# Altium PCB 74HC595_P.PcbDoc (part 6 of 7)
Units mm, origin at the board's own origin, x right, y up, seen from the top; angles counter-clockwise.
Board outline 89.11 x 89.03 mm, 2 copper layers (Top Layer, Bottom Layer); 552 components, 23 nets, 1488 pads, 408 vias.
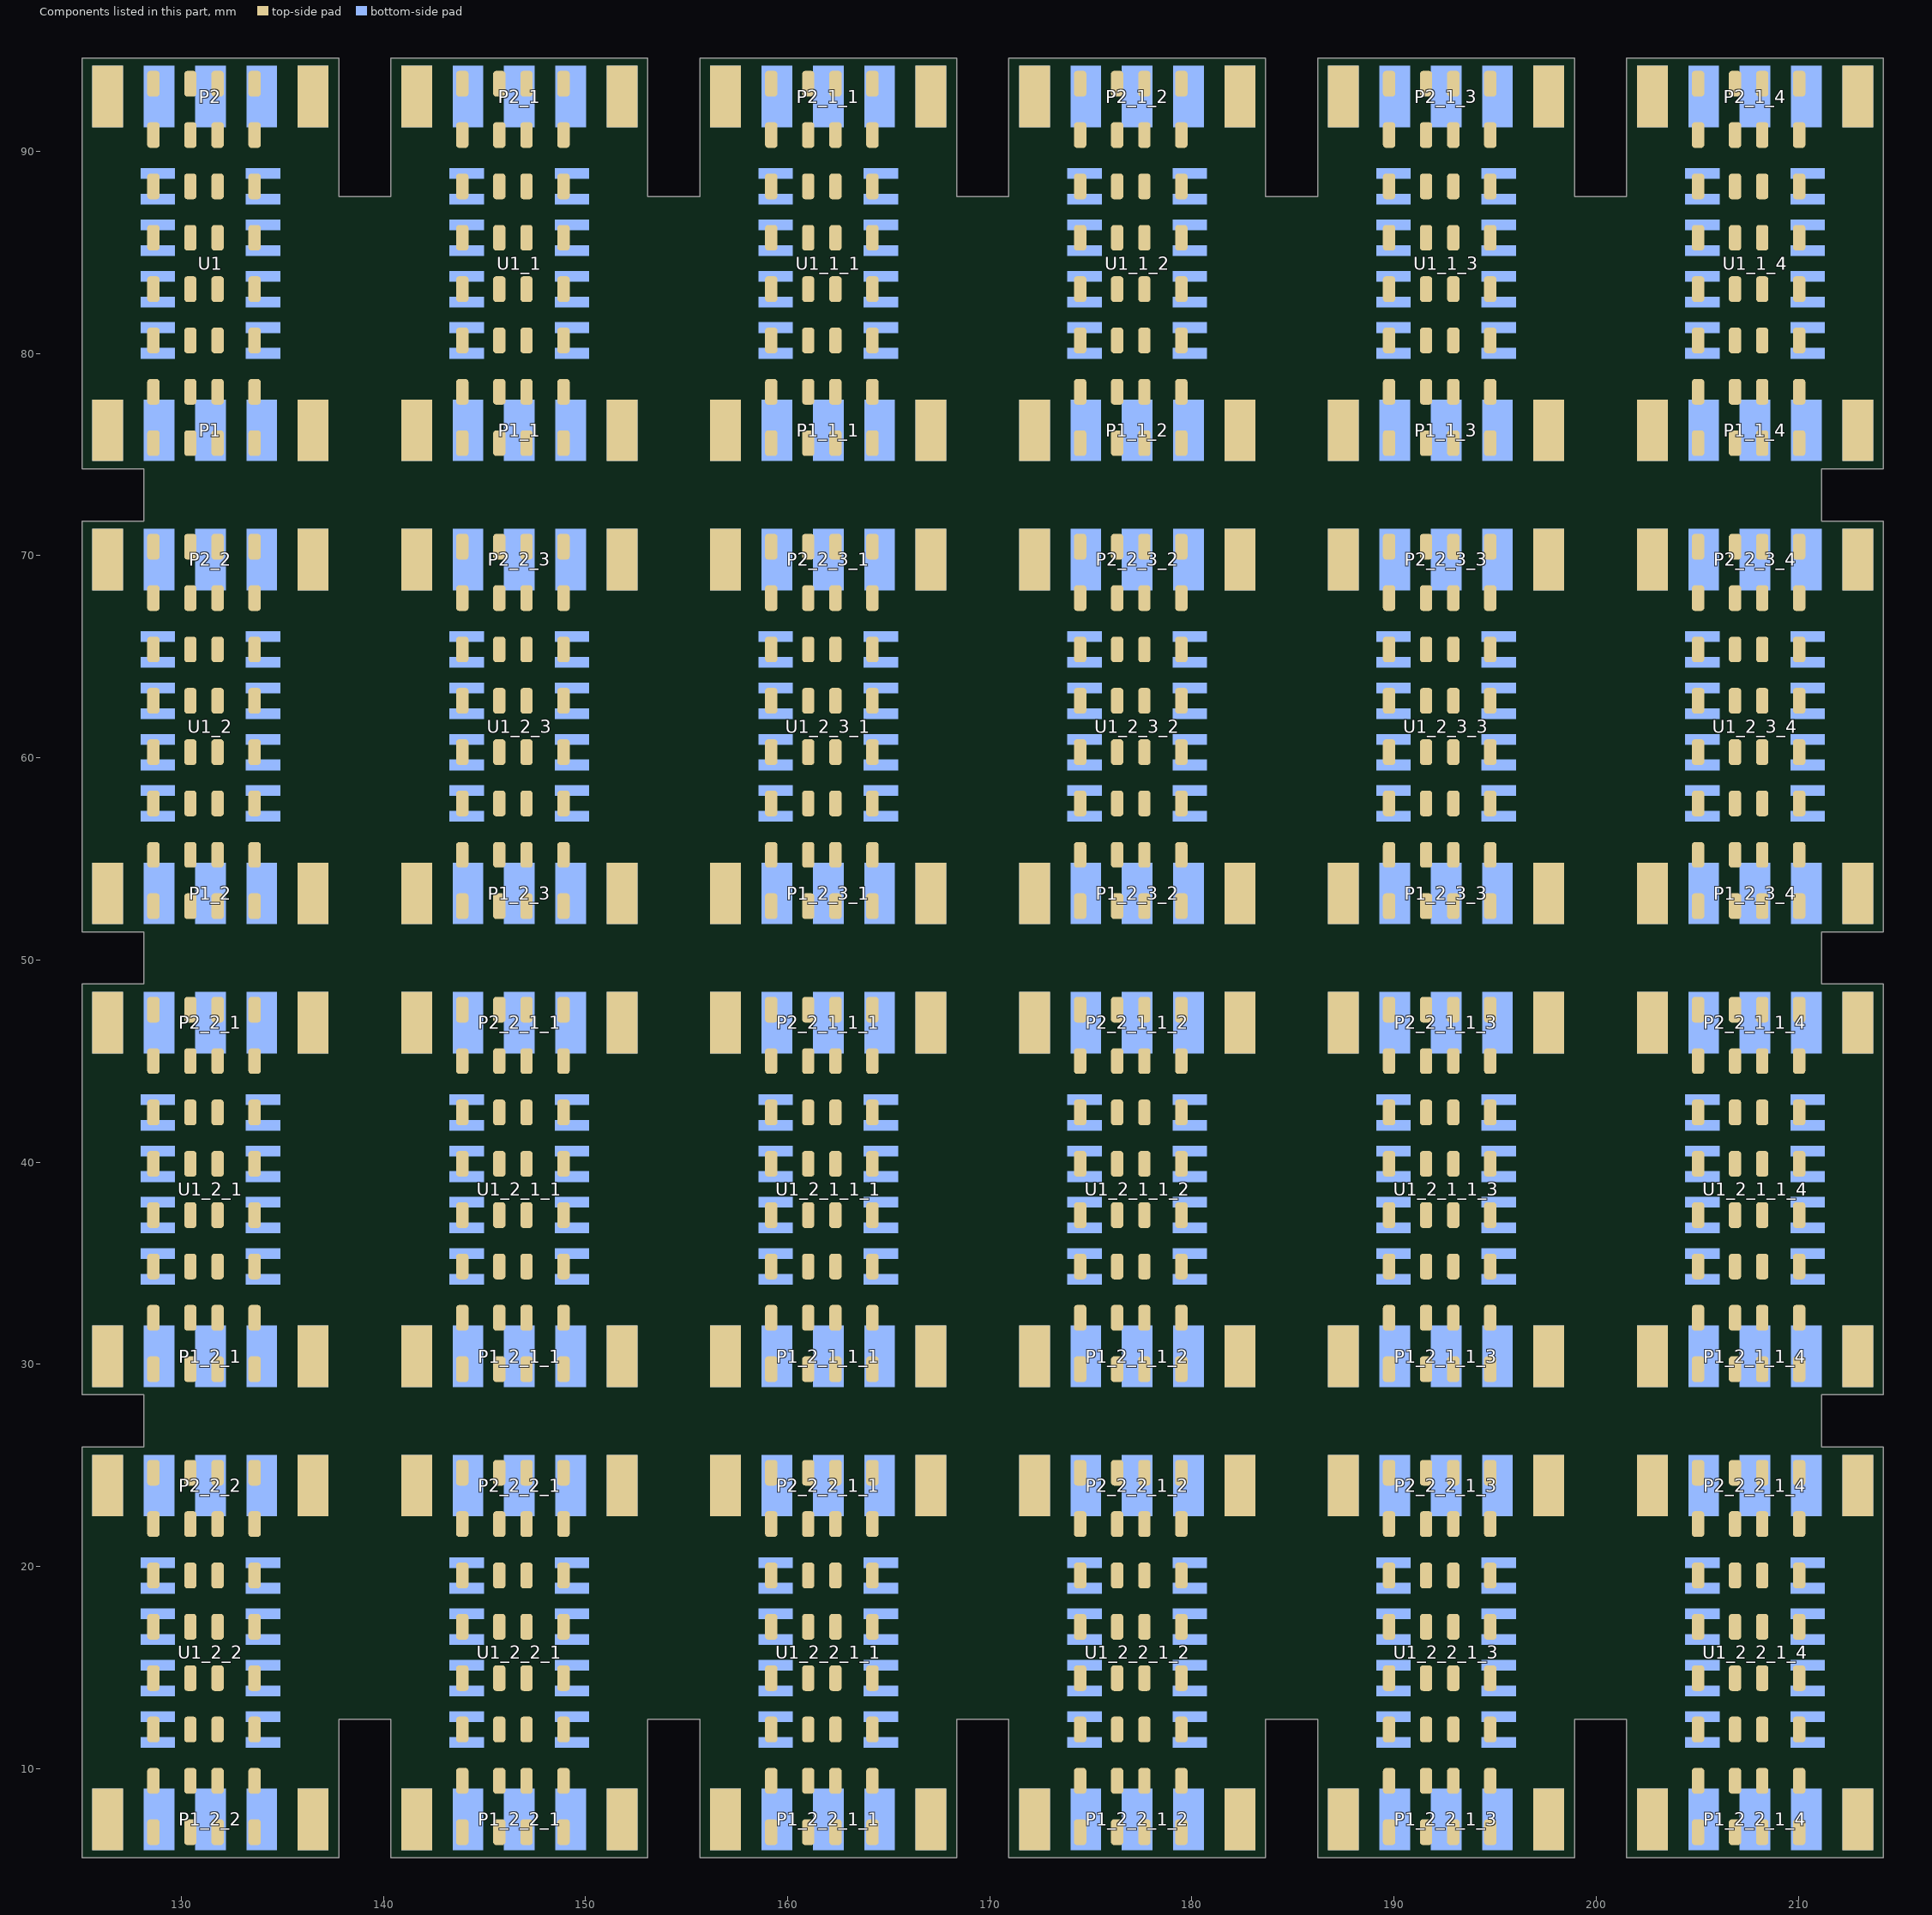
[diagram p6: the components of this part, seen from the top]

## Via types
v1: diameter 0.635, hole 0.381, Top Layer to Bottom Layer, 408 vias

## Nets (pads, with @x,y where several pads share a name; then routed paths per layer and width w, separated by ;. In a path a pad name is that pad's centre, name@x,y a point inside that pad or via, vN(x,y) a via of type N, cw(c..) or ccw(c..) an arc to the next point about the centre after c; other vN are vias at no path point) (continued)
copper on no net: (continued)
  Bottom Layer w0.381: 125.857,8.129 125.857,23.369 ; 125.857,31.031 125.857,46.271 ; 125.857,53.933 125.857,69.173 ; 125.984,17.654 128.841,17.654 ; 125.984,40.556 128.841,40.556 ; 125.984,63.458 128.841,63.458 ; v1(126.746,16.765) 126.746,11.685 127.127,11.304 128.841,11.304 128.841,7.558 ; v1(126.746,18.67) 126.746,21.21 128.905,23.369 128.905,24.004 ; v1(126.746,39.667) 126.746,34.587 127.127,34.206 128.841,34.206 128.841,30.46 ; v1(126.746,41.572) 126.746,44.112 128.905,46.271 128.905,46.906 ; v1(126.746,62.569) 126.746,57.489 127.127,57.108 128.841,57.108 128.841,53.362 ; v1(126.746,64.474) 126.746,67.014 128.905,69.173 128.905,69.808 ; v1(127.508,15.749) 127.508,13.971 127.635,13.844 128.841,13.844 130.048,13.844 131.064,12.828 131.064,7.875 131.445,7.494 ; v1(127.508,19.559) 127.508,21.074 128.152,21.718 129.921,21.718 131.445,23.242 131.445,24.004 ; v1(127.508,38.651) 127.508,36.873 127.635,36.746 128.841,36.746 130.048,36.746 131.064,35.73 131.064,30.777 131.445,30.396 ; v1(127.508,42.461) 127.508,43.976 128.152,44.62 129.921,44.62 131.445,46.144 131.445,46.906 ; v1(127.508,61.553) 127.508,59.775 127.635,59.648 128.841,59.648 130.048,59.648 131.064,58.632 131.064,53.679 131.445,53.298 ; v1(127.508,65.363) 127.508,66.878 128.152,67.522 129.921,67.522 131.445,69.046 131.445,69.808 ; 128.841,15.114 130.556,15.114 v1(131.191,15.749) 131.826,15.114 131.826,10.161 133.985,8.002 ; 128.841,16.384 130.048,16.384 130.683,17.019 131.953,17.019 132.461,16.511 132.461,10.669 133.35,9.78 137.033,9.78 ; 128.841,18.924 130.937,18.924 133.477,21.464 v1(135.89,21.464) ; 128.841,38.016 130.556,38.016 v1(131.191,38.651) 131.826,38.016 131.826,33.063 133.985,30.904 ; 128.841,39.286 130.048,39.286 130.683,39.921 131.953,39.921 132.461,39.413 132.461,33.571 133.35,32.682 137.033,32.682 ; 128.841,41.826 130.937,41.826 133.477,44.366 v1(135.89,44.366) ; 128.841,60.918 130.556,60.918 v1(131.191,61.553) 131.826,60.918 131.826,55.965 133.985,53.806 ; 128.841,62.188 130.048,62.188 130.683,62.823 131.953,62.823 132.461,62.315 132.461,56.473 133.35,55.584 137.033,55.584 ; 128.841,64.728 130.937,64.728 133.477,67.268 v1(135.89,67.268) ; 128.905,7.494 128.905,8.383 ; 128.905,30.396 128.905,31.285 ; 128.905,53.298 128.905,54.187 ; v1(131.191,20.829) 131.572,20.829 133.985,23.242 133.985,24.004 ; v1(131.191,43.731) 131.572,43.731 133.985,46.144 133.985,46.906 ; v1(131.191,66.633) 131.572,66.633 133.985,69.046 133.985,69.808 ; 134.048,11.304 v1(135.89,11.304) ; 134.048,12.574 v1(135.89,12.574) ; 134.048,13.844 v1(136.017,13.844) ; 134.048,15.114 v1(135.89,15.114) ; 134.048,16.384 v1(135.89,16.384) ; 134.048,17.654 v1(135.89,17.654) ; 134.048,18.924 v1(135.89,18.924) ; 134.048,20.194 v1(135.89,20.194) ; 134.048,34.206 v1(135.89,34.206) ; 134.048,35.476 v1(135.89,35.476) ; 134.048,36.746 v1(136.017,36.746) ; 134.048,38.016 v1(135.89,38.016) ; 134.048,39.286 v1(135.89,39.286) ; 134.048,40.556 v1(135.89,40.556) ; 134.048,41.826 v1(135.89,41.826) ; 134.048,43.096 v1(135.89,43.096) ; 134.048,57.108 v1(135.89,57.108) ; 134.048,58.378 v1(135.89,58.378) ; 134.048,59.648 v1(136.017,59.648) ; 134.048,60.918 v1(135.89,60.918) ; 134.048,62.188 v1(135.89,62.188) ; 134.048,63.458 v1(135.89,63.458) ; 134.048,64.728 v1(135.89,64.728) ; 134.048,65.998 v1(135.89,65.998) ; 137.033,8.129 137.033,9.78 ; 137.033,23.369 137.033,9.78 ; 137.033,31.031 137.033,32.682 ; 137.033,46.271 137.033,32.682 ; 137.033,53.933 137.033,55.584 ; 137.033,69.173 137.033,55.584 ; 141.139,8.129 141.139,23.369 ; 141.139,31.031 141.139,46.271 ; 141.139,53.933 141.139,69.173 ; 141.139,76.835 141.139,92.075 ; 141.266,17.654 144.123,17.654 ; 141.266,40.556 144.123,40.556 ; 141.266,63.458 144.123,63.458 ; 141.266,86.36 144.123,86.36 ; v1(142.028,16.765) 142.028,11.685 142.409,11.304 144.123,11.304 144.123,7.558 ; v1(142.028,18.67) 142.028,21.21 144.187,23.369 144.187,24.004 ; v1(142.028,39.667) 142.028,34.587 142.409,34.206 144.123,34.206 144.123,30.46 ; v1(142.028,41.572) 142.028,44.112 144.187,46.271 144.187,46.906 ; v1(142.028,62.569) 142.028,57.489 142.409,57.108 144.123,57.108 144.123,53.362 ; v1(142.028,64.474) 142.028,67.014 144.187,69.173 144.187,69.808 ; v1(142.028,85.471) 142.028,80.391 142.409,80.01 144.123,80.01 144.123,76.263 ; v1(142.028,87.376) 142.028,89.916 144.187,92.075 144.187,92.71 ; v1(142.79,15.749) 142.79,13.971 142.917,13.844 144.123,13.844 145.33,13.844 146.346,12.828 146.346,7.875 146.727,7.494 ; v1(142.79,19.559) 142.79,21.074 143.434,21.718 145.203,21.718 146.727,23.242 146.727,24.004 ; v1(142.79,38.651) 142.79,36.873 142.917,36.746 144.123,36.746 145.33,36.746 146.346,35.73 146.346,30.777 146.727,30.396 ; v1(142.79,42.461) 142.79,43.976 143.434,44.62 145.203,44.62 146.727,46.144 146.727,46.906 ; v1(142.79,61.553) 142.79,59.775 142.917,59.648 144.123,59.648 145.33,59.648 146.346,58.632 146.346,53.679 146.727,53.298 ; v1(142.79,65.363) 142.79,66.878 143.434,67.522 145.203,67.522 146.727,69.046 146.727,69.808 ; v1(142.79,84.455) 142.79,82.677 142.917,82.55 144.123,82.55 145.33,82.55 146.346,81.534 146.346,76.581 146.727,76.2 ; v1(142.79,88.265) 142.79,89.78 143.434,90.424 145.203,90.424 146.727,91.948 146.727,92.71 ; 144.123,15.114 145.838,15.114 v1(146.473,15.749) 147.108,15.114 147.108,10.161 149.267,8.002 ; 144.123,16.384 145.33,16.384 145.965,17.019 147.235,17.019 147.743,16.511 147.743,10.669 148.632,9.78 152.315,9.78 ; 144.123,18.924 146.219,18.924 148.759,21.464 v1(151.172,21.464) ; 144.123,38.016 145.838,38.016 v1(146.473,38.651) 147.108,38.016 147.108,33.063 149.267,30.904 ; 144.123,39.286 145.33,39.286 145.965,39.921 147.235,39.921 147.743,39.413 147.743,33.571 148.632,32.682 152.315,32.682 ; 144.123,41.826 146.219,41.826 148.759,44.366 v1(151.172,44.366) ; 144.123,60.918 145.838,60.918 v1(146.473,61.553) 147.108,60.918 147.108,55.965 149.267,53.806 ; 144.123,62.188 145.33,62.188 145.965,62.823 147.235,62.823 147.743,62.315 147.743,56.473 148.632,55.584 152.315,55.584 ; 144.123,64.728 146.219,64.728 148.759,67.268 v1(151.172,67.268) ; 144.123,83.82 145.838,83.82 v1(146.473,84.455) 147.108,83.82 147.108,78.867 149.267,76.708 ; 144.123,85.09 145.33,85.09 145.965,85.725 147.235,85.725 147.743,85.217 147.743,79.375 148.632,78.486 152.315,78.486 ; 144.123,87.63 146.219,87.63 148.759,90.17 v1(151.172,90.17) ; 144.187,7.494 144.187,8.383 ; 144.187,30.396 144.187,31.285 ; 144.187,53.298 144.187,54.187 ; 144.187,76.2 144.187,77.089 ; v1(146.473,20.829) 146.854,20.829 149.267,23.242 149.267,24.004 ; v1(146.473,43.731) 146.854,43.731 149.267,46.144 149.267,46.906 ; v1(146.473,66.633) 146.854,66.633 149.267,69.046 149.267,69.808 ; v1(146.473,89.535) 146.854,89.535 149.267,91.948 149.267,92.71 ; 149.33,11.304 v1(151.172,11.304) ; 149.33,12.574 v1(151.172,12.574) ; 149.33,13.844 v1(151.299,13.844) ; 149.33,15.114 v1(151.172,15.114) ; 149.33,16.384 v1(151.172,16.384) ; 149.33,17.654 v1(151.172,17.654) ; 149.33,18.924 v1(151.172,18.924) ; 149.33,20.194 v1(151.172,20.194) ; 149.33,34.206 v1(151.172,34.206) ; 149.33,35.476 v1(151.172,35.476) ; 149.33,36.746 v1(151.299,36.746) ; 149.33,38.016 v1(151.172,38.016) ; 149.33,39.286 v1(151.172,39.286) ; 149.33,40.556 v1(151.172,40.556) ; 149.33,41.826 v1(151.172,41.826) ; 149.33,43.096 v1(151.172,43.096) ; 149.33,57.108 v1(151.172,57.108) ; 149.33,58.378 v1(151.172,58.378) ; 149.33,59.648 v1(151.299,59.648) ; 149.33,60.918 v1(151.172,60.918) ; 149.33,62.188 v1(151.172,62.188) ; 149.33,63.458 v1(151.172,63.458) ; 149.33,64.728 v1(151.172,64.728) ; 149.33,65.998 v1(151.172,65.998) ; 149.33,80.01 v1(151.172,80.01) ; 149.33,81.28 v1(151.172,81.28) ; 149.33,82.55 v1(151.299,82.55) ; 149.33,83.82 v1(151.172,83.82) ; 149.33,85.09 v1(151.172,85.09) ; 149.33,86.36 v1(151.172,86.36) ; 149.33,87.63 v1(151.172,87.63) ; 149.33,88.9 v1(151.172,88.9) ; 152.315,8.129 152.315,9.78 ; 152.315,23.369 152.315,9.78 ; 152.315,31.031 152.315,32.682 ; 152.315,46.271 152.315,32.682 ; 152.315,53.933 152.315,55.584 ; 152.315,69.173 152.315,55.584 ; 152.315,76.835 152.315,78.486 ; 152.315,92.075 152.315,78.486 ; 156.421,8.129 156.421,23.369 ; 156.421,31.031 156.421,46.271 ; 156.421,53.933 156.421,69.173 ; 156.421,76.835 156.421,92.075 ; 156.548,17.654 159.405,17.654 ; 156.548,40.556 159.405,40.556 ; 156.548,63.458 159.405,63.458 ; 156.548,86.36 159.405,86.36 ; v1(157.31,16.765) 157.31,11.685 157.691,11.304 159.405,11.304 159.405,7.558 ; v1(157.31,18.67) 157.31,21.21 159.469,23.369 159.469,24.004 ; v1(157.31,39.667) 157.31,34.587 157.691,34.206 159.405,34.206 159.405,30.46 ; v1(157.31,41.572) 157.31,44.112 159.469,46.271 159.469,46.906 ; v1(157.31,62.569) 157.31,57.489 157.691,57.108 159.405,57.108 159.405,53.362 ; v1(157.31,64.474) 157.31,67.014 159.469,69.173 159.469,69.808 ; v1(157.31,85.471) 157.31,80.391 157.691,80.01 159.405,80.01 159.405,76.263 ; v1(157.31,87.376) 157.31,89.916 159.469,92.075 159.469,92.71 ; v1(158.072,15.749) 158.072,13.971 158.199,13.844 159.405,13.844 160.612,13.844 161.628,12.828 161.628,7.875 162.009,7.494 ; v1(158.072,19.559) 158.072,21.074 158.716,21.718 160.485,21.718 162.009,23.242 162.009,24.004 ; v1(158.072,38.651) 158.072,36.873 158.199,36.746 159.405,36.746 160.612,36.746 161.628,35.73 161.628,30.777 162.009,30.396 ; v1(158.072,42.461) 158.072,43.976 158.716,44.62 160.485,44.62 162.009,46.144 162.009,46.906 ; v1(158.072,61.553) 158.072,59.775 158.199,59.648 159.405,59.648 160.612,59.648 161.628,58.632 161.628,53.679 162.009,53.298 ; v1(158.072,65.363) 158.072,66.878 158.716,67.522 160.485,67.522 162.009,69.046 162.009,69.808 ; v1(158.072,84.455) 158.072,82.677 158.199,82.55 159.405,82.55 160.612,82.55 161.628,81.534 161.628,76.581 162.009,76.2 ; v1(158.072,88.265) 158.072,89.78 158.716,90.424 160.485,90.424 162.009,91.948 162.009,92.71 ; 159.405,15.114 161.12,15.114 v1(161.755,15.749) 162.39,15.114 162.39,10.161 164.549,8.002 ; 159.405,16.384 160.612,16.384 161.247,17.019 162.517,17.019 163.025,16.511 163.025,10.669 163.914,9.78 167.597,9.78 ; 159.405,18.924 161.501,18.924 164.041,21.464 v1(166.454,21.464) ; 159.405,38.016 161.12,38.016 v1(161.755,38.651) 162.39,38.016 162.39,33.063 164.549,30.904 ; 159.405,39.286 160.612,39.286 161.247,39.921 162.517,39.921 163.025,39.413 163.025,33.571 163.914,32.682 167.597,32.682 ; 159.405,41.826 161.501,41.826 164.041,44.366 v1(166.454,44.366) ; 159.405,60.918 161.12,60.918 v1(161.755,61.553) 162.39,60.918 162.39,55.965 164.549,53.806 ; 159.405,62.188 160.612,62.188 161.247,62.823 162.517,62.823 163.025,62.315 163.025,56.473 163.914,55.584 167.597,55.584 ; 159.405,64.728 161.501,64.728 164.041,67.268 v1(166.454,67.268) ; 159.405,83.82 161.12,83.82 v1(161.755,84.455) 162.39,83.82 162.39,78.867 164.549,76.708 ; 159.405,85.09 160.612,85.09 161.247,85.725 162.517,85.725 163.025,85.217 163.025,79.375 163.914,78.486 167.597,78.486 ; 159.405,87.63 161.501,87.63 164.041,90.17 v1(166.454,90.17) ; 159.469,7.494 159.469,8.383 ; 159.469,30.396 159.469,31.285 ; 159.469,53.298 159.469,54.187 ; 159.469,76.2 159.469,77.089 ; v1(161.755,20.829) 162.136,20.829 164.549,23.242 164.549,24.004 ; v1(161.755,43.731) 162.136,43.731 164.549,46.144 164.549,46.906 ; v1(161.755,66.633) 162.136,66.633 164.549,69.046 164.549,69.808 ; v1(161.755,89.535) 162.136,89.535 164.549,91.948 164.549,92.71 ; 164.612,11.304 v1(166.454,11.304) ; 164.612,12.574 v1(166.454,12.574) ; 164.612,13.844 v1(166.581,13.844) ; 164.612,15.114 v1(166.454,15.114) ; 164.612,16.384 v1(166.454,16.384) ; 164.612,17.654 v1(166.454,17.654) ; 164.612,18.924 v1(166.454,18.924) ; 164.612,20.194 v1(166.454,20.194) ; 164.612,34.206 v1(166.454,34.206) ; 164.612,35.476 v1(166.454,35.476) ; 164.612,36.746 v1(166.581,36.746) ; 164.612,38.016 v1(166.454,38.016) ; 164.612,39.286 v1(166.454,39.286) ; 164.612,40.556 v1(166.454,40.556) ; 164.612,41.826 v1(166.454,41.826) ; 164.612,43.096 v1(166.454,43.096) ; 164.612,57.108 v1(166.454,57.108) ; 164.612,58.378 v1(166.454,58.378) ; 164.612,59.648 v1(166.581,59.648) ; 164.612,60.918 v1(166.454,60.918) ; 164.612,62.188 v1(166.454,62.188) ; 164.612,63.458 v1(166.454,63.458) ; 164.612,64.728 v1(166.454,64.728) ; 164.612,65.998 v1(166.454,65.998) ; 164.612,80.01 v1(166.454,80.01) ; 164.612,81.28 v1(166.454,81.28) ; 164.612,82.55 v1(166.581,82.55) ; 164.612,83.82 v1(166.454,83.82) ; 164.612,85.09 v1(166.454,85.09) ; 164.612,86.36 v1(166.454,86.36) ; 164.612,87.63 v1(166.454,87.63) ; 164.612,88.9 v1(166.454,88.9) ; 167.597,8.129 167.597,9.78 ; 167.597,23.369 167.597,9.78 ; 167.597,31.031 167.597,32.682 ; 167.597,46.271 167.597,32.682 ; 167.597,53.933 167.597,55.584 ; 167.597,69.173 167.597,55.584 ; 167.597,76.835 167.597,78.486 ; 167.597,92.075 167.597,78.486 ; 171.703,8.129 171.703,23.369 ; 171.703,31.031 171.703,46.271 ; 171.703,53.933 171.703,69.173 ; 171.703,76.835 171.703,92.075 ; 171.83,17.654 174.687,17.654 ; 171.83,40.556 174.687,40.556 ; 171.83,63.458 174.687,63.458 ; 171.83,86.36 174.687,86.36 ; v1(172.592,16.765) 172.592,11.685 172.973,11.304 174.687,11.304 174.687,7.558 ; v1(172.592,18.67) 172.592,21.21 174.751,23.369 174.751,24.004 ; v1(172.592,39.667) 172.592,34.587 172.973,34.206 174.687,34.206 174.687,30.46 ; v1(172.592,41.572) 172.592,44.112 174.751,46.271 174.751,46.906 ; v1(172.592,62.569) 172.592,57.489 172.973,57.108 174.687,57.108 174.687,53.362 ; v1(172.592,64.474) 172.592,67.014 174.751,69.173 174.751,69.808 ; v1(172.592,85.471) 172.592,80.391 172.973,80.01 174.687,80.01 174.687,76.263 ; v1(172.592,87.376) 172.592,89.916 174.751,92.075 174.751,92.71 ; v1(173.354,15.749) 173.354,13.971 173.481,13.844 174.687,13.844 175.894,13.844 176.91,12.828 176.91,7.875 177.291,7.494 ; v1(173.354,19.559) 173.354,21.074 173.998,21.718 175.767,21.718 177.291,23.242 177.291,24.004 ; v1(173.354,38.651) 173.354,36.873 173.481,36.746 174.687,36.746 175.894,36.746 176.91,35.73 176.91,30.777 177.291,30.396 ; v1(173.354,42.461) 173.354,43.976 173.998,44.62 175.767,44.62 177.291,46.144 177.291,46.906 ; v1(173.354,61.553) 173.354,59.775 173.481,59.648 174.687,59.648 175.894,59.648 176.91,58.632 176.91,53.679 177.291,53.298 ; v1(173.354,65.363) 173.354,66.878 173.998,67.522 175.767,67.522 177.291,69.046 177.291,69.808 ; v1(173.354,84.455) 173.354,82.677 173.481,82.55 174.687,82.55 175.894,82.55 176.91,81.534 176.91,76.581 177.291,76.2 ; v1(173.354,88.265) 173.354,89.78 173.998,90.424 175.767,90.424 177.291,91.948 177.291,92.71 ; 174.687,15.114 176.402,15.114 v1(177.037,15.749) 177.672,15.114 177.672,10.161 179.831,8.002 ; 174.687,16.384 175.894,16.384 176.529,17.019 177.799,17.019 178.307,16.511 178.307,10.669 179.196,9.78 182.879,9.78 ; 174.687,18.924 176.783,18.924 179.323,21.464 v1(181.736,21.464) ; 174.687,38.016 176.402,38.016 v1(177.037,38.651) 177.672,38.016 177.672,33.063 179.831,30.904 ; 174.687,39.286 175.894,39.286 176.529,39.921 177.799,39.921 178.307,39.413 178.307,33.571 179.196,32.682 182.879,32.682 ; 174.687,41.826 176.783,41.826 179.323,44.366 v1(181.736,44.366) ; 174.687,60.918 176.402,60.918 v1(177.037,61.553) 177.672,60.918 177.672,55.965 179.831,53.806 ; 174.687,62.188 175.894,62.188 176.529,62.823 177.799,62.823 178.307,62.315 178.307,56.473 179.196,55.584 182.879,55.584 ; 174.687,64.728 176.783,64.728 179.323,67.268 v1(181.736,67.268) ; 174.687,83.82 176.402,83.82 v1(177.037,84.455) 177.672,83.82 177.672,78.867 179.831,76.708 ; 174.687,85.09 175.894,85.09 176.529,85.725 177.799,85.725 178.307,85.217 178.307,79.375 179.196,78.486 182.879,78.486 ; 174.687,87.63 176.783,87.63 179.323,90.17 v1(181.736,90.17) ; 174.751,7.494 174.751,8.383 ; 174.751,30.396 174.751,31.285 ; 174.751,53.298 174.751,54.187 ; 174.751,76.2 174.751,77.089 ; v1(177.037,20.829) 177.418,20.829 179.831,23.242 179.831,24.004 ; v1(177.037,43.731) 177.418,43.731 179.831,46.144 179.831,46.906 ; v1(177.037,66.633) 177.418,66.633 179.831,69.046 179.831,69.808 ; v1(177.037,89.535) 177.418,89.535 179.831,91.948 179.831,92.71 ; 179.894,11.304 v1(181.736,11.304) ; 179.894,12.574 v1(181.736,12.574) ; 179.894,13.844 v1(181.863,13.844) ; 179.894,15.114 v1(181.736,15.114) ; 179.894,16.384 v1(181.736,16.384) ; 179.894,17.654 v1(181.736,17.654) ; 179.894,18.924 v1(181.736,18.924) ; 179.894,20.194 v1(181.736,20.194) ; 179.894,34.206 v1(181.736,34.206) ; 179.894,35.476 v1(181.736,35.476) ; 179.894,36.746 v1(181.863,36.746) ; 179.894,38.016 v1(181.736,38.016) ; 179.894,39.286 v1(181.736,39.286) ; 179.894,40.556 v1(181.736,40.556) ; 179.894,41.826 v1(181.736,41.826) ; 179.894,43.096 v1(181.736,43.096) ; 179.894,57.108 v1(181.736,57.108) ; 179.894,58.378 v1(181.736,58.378) ; 179.894,59.648 v1(181.863,59.648) ; 179.894,60.918 v1(181.736,60.918) ; 179.894,62.188 v1(181.736,62.188) ; 179.894,63.458 v1(181.736,63.458) ; 179.894,64.728 v1(181.736,64.728) ; 179.894,65.998 v1(181.736,65.998) ; 179.894,80.01 v1(181.736,80.01) ; 179.894,81.28 v1(181.736,81.28) ; 179.894,82.55 v1(181.863,82.55) ; 179.894,83.82 v1(181.736,83.82) ; 179.894,85.09 v1(181.736,85.09) ; 179.894,86.36 v1(181.736,86.36) ; 179.894,87.63 v1(181.736,87.63) ; 179.894,88.9 v1(181.736,88.9) ; 182.879,8.129 182.879,9.78 ; 182.879,23.369 182.879,9.78 ; 182.879,31.031 182.879,32.682 ; 182.879,46.271 182.879,32.682 ; 182.879,53.933 182.879,55.584 ; 182.879,69.173 182.879,55.584 ; 182.879,76.835 182.879,78.486 ; 182.879,92.075 182.879,78.486 ; 186.985,8.129 186.985,23.369 ; 186.985,31.031 186.985,46.271 ; 186.985,53.933 186.985,69.173 ; 186.985,76.835 186.985,92.075 ; 187.112,17.654 189.969,17.654 ; 187.112,40.556 189.969,40.556 ; 187.112,63.458 189.969,63.458 ; 187.112,86.36 189.969,86.36 ; v1(187.874,16.765) 187.874,11.685 188.255,11.304 189.969,11.304 189.969,7.558 ; v1(187.874,18.67) 187.874,21.21 190.033,23.369 190.033,24.004 ; v1(187.874,39.667) 187.874,34.587 188.255,34.206 189.969,34.206 189.969,30.46 ; v1(187.874,41.572) 187.874,44.112 190.033,46.271 190.033,46.906 ; v1(187.874,62.569) 187.874,57.489 188.255,57.108 189.969,57.108 189.969,53.362 ; v1(187.874,64.474) 187.874,67.014 190.033,69.173 190.033,69.808 ; v1(187.874,85.471) 187.874,80.391 188.255,80.01 189.969,80.01 189.969,76.263 ; v1(187.874,87.376) 187.874,89.916 190.033,92.075 190.033,92.71 ; v1(188.636,15.749) 188.636,13.971 188.763,13.844 189.969,13.844 191.176,13.844 192.192,12.828 192.192,7.875 192.573,7.494 ; v1(188.636,19.559) 188.636,21.074 189.28,21.718 191.049,21.718 192.573,23.242 192.573,24.004 ; v1(188.636,38.651) 188.636,36.873 188.763,36.746 189.969,36.746 191.176,36.746 192.192,35.73 192.192,30.777 192.573,30.396 ; v1(188.636,42.461) 188.636,43.976 189.28,44.62 191.049,44.62 192.573,46.144 192.573,46.906 ; v1(188.636,61.553) 188.636,59.775 188.763,59.648 189.969,59.648 191.176,59.648 192.192,58.632 192.192,53.679 192.573,53.298 ; v1(188.636,65.363) 188.636,66.878 189.28,67.522 191.049,67.522 192.573,69.046 192.573,69.808 ; v1(188.636,84.455) 188.636,82.677 188.763,82.55 189.969,82.55 191.176,82.55 192.192,81.534 192.192,76.581 192.573,76.2 ; v1(188.636,88.265) 188.636,89.78 189.28,90.424 191.049,90.424 192.573,91.948 192.573,92.71 ; 189.969,15.114 191.684,15.114 v1(192.319,15.749) 192.954,15.114 192.954,10.161 195.113,8.002 ; 189.969,16.384 191.176,16.384 191.811,17.019 193.081,17.019 193.589,16.511 193.589,10.669 194.478,9.78 198.161,9.78 ; 189.969,18.924 192.065,18.924 194.605,21.464 v1(197.018,21.464) ; 189.969,38.016 191.684,38.016 v1(192.319,38.651) 192.954,38.016 192.954,33.063 195.113,30.904 ; 189.969,39.286 191.176,39.286 191.811,39.921 193.081,39.921 193.589,39.413 193.589,33.571 194.478,32.682 198.161,32.682 ; 189.969,41.826 192.065,41.826 194.605,44.366 v1(197.018,44.366) ; 189.969,60.918 191.684,60.918 v1(192.319,61.553) 192.954,60.918 192.954,55.965 195.113,53.806 ; 189.969,62.188 191.176,62.188 191.811,62.823 193.081,62.823 193.589,62.315 193.589,56.473 194.478,55.584 198.161,55.584 ; 189.969,64.728 192.065,64.728 194.605,67.268 v1(197.018,67.268) ; 189.969,83.82 191.684,83.82 v1(192.319,84.455) 192.954,83.82 192.954,78.867 195.113,76.708 ; 189.969,85.09 191.176,85.09 191.811,85.725 193.081,85.725 193.589,85.217 193.589,79.375 194.478,78.486 198.161,78.486 ; 189.969,87.63 192.065,87.63 194.605,90.17 v1(197.018,90.17) ; 190.033,7.494 190.033,8.383 ; 190.033,30.396 190.033,31.285 ; 190.033,53.298 190.033,54.187 ; 190.033,76.2 190.033,77.089 ; v1(192.319,20.829) 192.7,20.829 195.113,23.242 195.113,24.004 ; v1(192.319,43.731) 192.7,43.731 195.113,46.144 195.113,46.906 ; v1(192.319,66.633) 192.7,66.633 195.113,69.046 195.113,69.808 ; v1(192.319,89.535) 192.7,89.535 195.113,91.948 195.113,92.71 ; 195.176,11.304 v1(197.018,11.304) ; 195.176,12.574 v1(197.018,12.574) ; 195.176,13.844 v1(197.145,13.844) ; 195.176,15.114 v1(197.018,15.114) ; 195.176,16.384 v1(197.018,16.384) ; 195.176,17.654 v1(197.018,17.654) ; 195.176,18.924 v1(197.018,18.924) ; 195.176,20.194 v1(197.018,20.194) ; 195.176,34.206 v1(197.018,34.206) ; 195.176,35.476 v1(197.018,35.476) ; 195.176,36.746 v1(197.145,36.746) ; 195.176,38.016 v1(197.018,38.016) ; 195.176,39.286 v1(197.018,39.286) ; 195.176,40.556 v1(197.018,40.556) ; 195.176,41.826 v1(197.018,41.826) ; 195.176,43.096 v1(197.018,43.096) ; 195.176,57.108 v1(197.018,57.108) ; 195.176,58.378 v1(197.018,58.378) ; 195.176,59.648 v1(197.145,59.648) ; 195.176,60.918 v1(197.018,60.918) ; 195.176,62.188 v1(197.018,62.188) ; 195.176,63.458 v1(197.018,63.458) ; 195.176,64.728 v1(197.018,64.728) ; 195.176,65.998 v1(197.018,65.998) ; 195.176,80.01 v1(197.018,80.01) ; 195.176,81.28 v1(197.018,81.28) ; 195.176,82.55 v1(197.145,82.55) ; 195.176,83.82 v1(197.018,83.82) ; 195.176,85.09 v1(197.018,85.09) ; 195.176,86.36 v1(197.018,86.36) ; 195.176,87.63 v1(197.018,87.63) ; 195.176,88.9 v1(197.018,88.9) ; 198.161,8.129 198.161,9.78 ; 198.161,23.369 198.161,9.78 ; 198.161,31.031 198.161,32.682 ; 198.161,46.271 198.161,32.682 ; 198.161,53.933 198.161,55.584 ; 198.161,69.173 198.161,55.584 ; 198.161,76.835 198.161,78.486 ; 198.161,92.075 198.161,78.486 ; 202.267,8.129 202.267,23.369 ; 202.267,31.031 202.267,46.271 ; 202.267,53.933 202.267,69.173 ; 202.267,76.835 202.267,92.075 ; 202.394,17.654 205.251,17.654 ; 202.394,40.556 205.251,40.556 ; 202.394,63.458 205.251,63.458 ; 202.394,86.36 205.251,86.36 ; v1(203.156,16.765) 203.156,11.685 203.537,11.304 205.251,11.304 205.251,7.558 ; v1(203.156,18.67) 203.156,21.21 205.315,23.369 205.315,24.004 ; v1(203.156,39.667) 203.156,34.587 203.537,34.206 205.251,34.206 205.251,30.46 ; v1(203.156,41.572) 203.156,44.112 205.315,46.271 205.315,46.906 ; v1(203.156,62.569) 203.156,57.489 203.537,57.108 205.251,57.108 205.251,53.362 ; v1(203.156,64.474) 203.156,67.014 205.315,69.173 205.315,69.808 ; v1(203.156,85.471) 203.156,80.391 203.537,80.01 205.251,80.01 205.251,76.263 ; v1(203.156,87.376) 203.156,89.916 205.315,92.075 205.315,92.71 ; v1(203.918,15.749) 203.918,13.971 204.045,13.844 205.251,13.844 206.458,13.844 207.474,12.828 207.474,7.875 207.855,7.494 ; v1(203.918,19.559) 203.918,21.074 204.562,21.718 206.331,21.718 207.855,23.242 207.855,24.004 ; v1(203.918,38.651) 203.918,36.873 204.045,36.746 205.251,36.746 206.458,36.746 207.474,35.73 207.474,30.777 207.855,30.396 ; v1(203.918,42.461) 203.918,43.976 204.562,44.62 206.331,44.62 207.855,46.144 207.855,46.906 ; v1(203.918,61.553) 203.918,59.775 204.045,59.648 205.251,59.648 206.458,59.648 207.474,58.632 207.474,53.679 207.855,53.298 ; v1(203.918,65.363) 203.918,66.878 204.562,67.522 206.331,67.522 207.855,69.046 207.855,69.808 ; v1(203.918,84.455) 203.918,82.677 204.045,82.55 205.251,82.55 206.458,82.55 207.474,81.534 207.474,76.581 207.855,76.2 ; v1(203.918,88.265) 203.918,89.78 204.562,90.424 206.331,90.424 207.855,91.948 207.855,92.71 ; 205.251,15.114 206.966,15.114 v1(207.601,15.749) 208.236,15.114 208.236,10.161 210.395,8.002 ; 205.251,16.384 206.458,16.384 207.093,17.019 208.363,17.019 208.871,16.511 208.871,10.669 209.76,9.78 213.443,9.78 ; 205.251,18.924 207.347,18.924 209.887,21.464 v1(212.3,21.464) ; 205.251,38.016 206.966,38.016 v1(207.601,38.651) 208.236,38.016 208.236,33.063 210.395,30.904 ; 205.251,39.286 206.458,39.286 207.093,39.921 208.363,39.921 208.871,39.413 208.871,33.571 209.76,32.682 213.443,32.682 ; 205.251,41.826 207.347,41.826 209.887,44.366 v1(212.3,44.366) ; 205.251,60.918 206.966,60.918 v1(207.601,61.553) 208.236,60.918 208.236,55.965 210.395,53.806 ; 205.251,62.188 206.458,62.188 207.093,62.823 208.363,62.823 208.871,62.315 208.871,56.473 209.76,55.584 213.443,55.584 ; 205.251,64.728 207.347,64.728 209.887,67.268 v1(212.3,67.268) ; 205.251,83.82 206.966,83.82 v1(207.601,84.455) 208.236,83.82 208.236,78.867 210.395,76.708 ; 205.251,85.09 206.458,85.09 207.093,85.725 208.363,85.725 208.871,85.217 208.871,79.375 209.76,78.486 213.443,78.486 ; 205.251,87.63 207.347,87.63 209.887,90.17 v1(212.3,90.17) ; 205.315,7.494 205.315,8.383 ; 205.315,30.396 205.315,31.285 ; 205.315,53.298 205.315,54.187 ; 205.315,76.2 205.315,77.089 ; v1(207.601,20.829) 207.982,20.829 210.395,23.242 210.395,24.004 ; v1(207.601,43.731) 207.982,43.731 210.395,46.144 210.395,46.906 ; v1(207.601,66.633) 207.982,66.633 210.395,69.046 210.395,69.808 ; v1(207.601,89.535) 207.982,89.535 210.395,91.948 210.395,92.71 ; 210.458,11.304 v1(212.3,11.304) ; 210.458,12.574 v1(212.3,12.574) ; 210.458,13.844 v1(212.427,13.844) ; 210.458,15.114 v1(212.3,15.114) ; 210.458,16.384 v1(212.3,16.384) ; 210.458,17.654 v1(212.3,17.654) ; 210.458,18.924 v1(212.3,18.924) ; 210.458,20.194 v1(212.3,20.194) ; 210.458,34.206 v1(212.3,34.206) ; 210.458,35.476 v1(212.3,35.476) ; 210.458,36.746 v1(212.427,36.746) ; 210.458,38.016 v1(212.3,38.016) ; 210.458,39.286 v1(212.3,39.286) ; 210.458,40.556 v1(212.3,40.556) ; 210.458,41.826 v1(212.3,41.826) ; 210.458,43.096 v1(212.3,43.096) ; 210.458,57.108 v1(212.3,57.108) ; 210.458,58.378 v1(212.3,58.378) ; 210.458,59.648 v1(212.427,59.648) ; 210.458,60.918 v1(212.3,60.918) ; 210.458,62.188 v1(212.3,62.188) ; 210.458,63.458 v1(212.3,63.458) ; 210.458,64.728 v1(212.3,64.728) ; 210.458,65.998 v1(212.3,65.998) ; 210.458,80.01 v1(212.3,80.01) ; 210.458,81.28 v1(212.3,81.28) ; 210.458,82.55 v1(212.427,82.55) ; 210.458,83.82 v1(212.3,83.82) ; 210.458,85.09 v1(212.3,85.09) ; 210.458,86.36 v1(212.3,86.36) ; 210.458,87.63 v1(212.3,87.63) ; 210.458,88.9 v1(212.3,88.9) ; 213.443,8.129 213.443,9.78 ; 213.443,23.369 213.443,9.78 ; 213.443,31.031 213.443,32.682 ; 213.443,46.271 213.443,32.682 ; 213.443,53.933 213.443,55.584 ; 213.443,69.173 213.443,55.584 ; 213.443,76.835 213.443,78.486 ; 213.443,92.075 213.443,78.486
  Bottom Layer w0.508: v1(127.635,12.574) 128.841,12.574 ; v1(127.635,35.476) 128.841,35.476 ; v1(127.635,58.378) 128.841,58.378 ; 128.626,20.41 v1(128.626,20.829) ; 128.626,43.312 v1(128.626,43.731) ; 128.626,66.214 v1(128.626,66.633) ; v1(142.917,12.574) 144.123,12.574 ; v1(142.917,35.476) 144.123,35.476 ; v1(142.917,58.378) 144.123,58.378 ; v1(142.917,81.28) 144.123,81.28 ; 143.908,20.41 v1(143.908,20.829) ; 143.908,43.312 v1(143.908,43.731) ; 143.908,66.214 v1(143.908,66.633) ; 143.908,89.116 v1(143.908,89.535) ; v1(158.199,12.574) 159.405,12.574 ; v1(158.199,35.476) 159.405,35.476 ; v1(158.199,58.378) 159.405,58.378 ; v1(158.199,81.28) 159.405,81.28 ; 159.19,20.41 v1(159.19,20.829) ; 159.19,43.312 v1(159.19,43.731) ; 159.19,66.214 v1(159.19,66.633) ; 159.19,89.116 v1(159.19,89.535) ; v1(173.481,12.574) 174.687,12.574 ; v1(173.481,35.476) 174.687,35.476 ; v1(173.481,58.378) 174.687,58.378 ; v1(173.481,81.28) 174.687,81.28 ; 174.472,20.41 v1(174.472,20.829) ; 174.472,43.312 v1(174.472,43.731) ; 174.472,66.214 v1(174.472,66.633) ; 174.472,89.116 v1(174.472,89.535) ; v1(188.763,12.574) 189.969,12.574 ; v1(188.763,35.476) 189.969,35.476 ; v1(188.763,58.378) 189.969,58.378 ; v1(188.763,81.28) 189.969,81.28 ; 189.754,20.41 v1(189.754,20.829) ; 189.754,43.312 v1(189.754,43.731) ; 189.754,66.214 v1(189.754,66.633) ; 189.754,89.116 v1(189.754,89.535) ; v1(204.045,12.574) 205.251,12.574 ; v1(204.045,35.476) 205.251,35.476 ; v1(204.045,58.378) 205.251,58.378 ; v1(204.045,81.28) 205.251,81.28 ; 205.036,20.41 v1(205.036,20.829) ; 205.036,43.312 v1(205.036,43.731) ; 205.036,66.214 v1(205.036,66.633) ; 205.036,89.116 v1(205.036,89.535)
